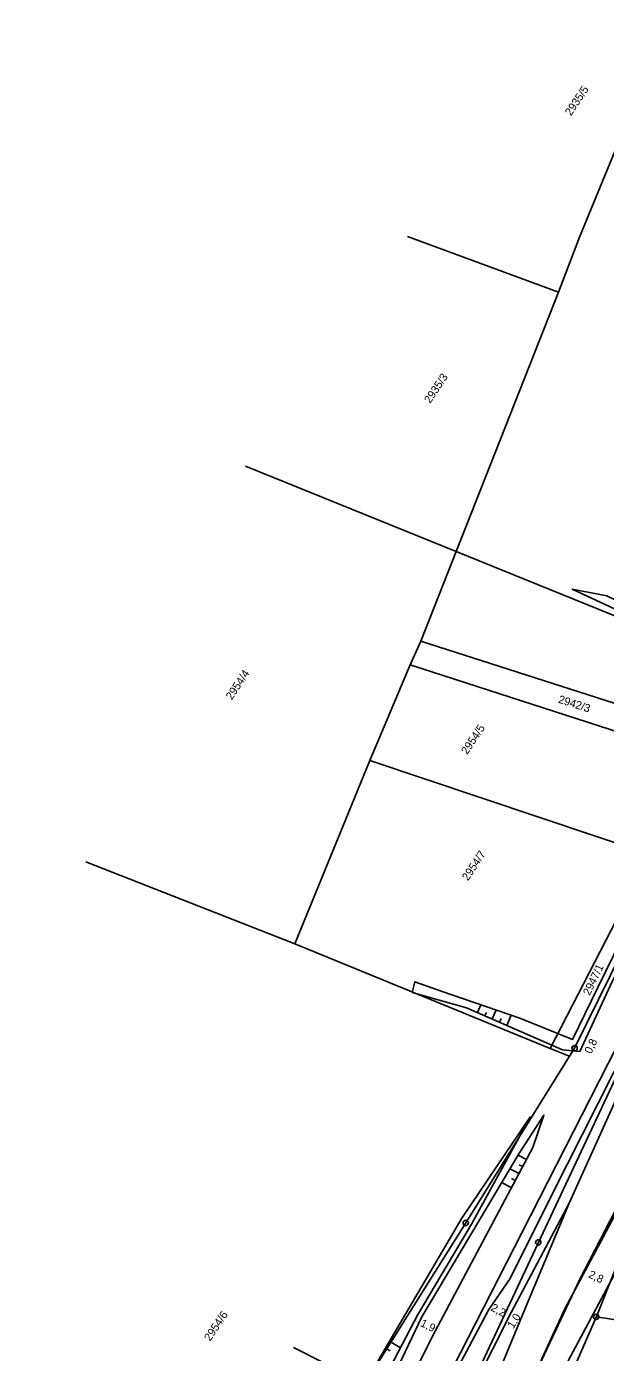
# Model space of a CAD drawing. Extents: x -658910 to -658078, y -1170373 to -1169331.
# Drawn here: x -658412.3 to -658303.7, y -1169709.4 to -1169460.8 of the extents above; entities that cross this region are included whole.
import ezdxf

# ---------------------------------------------------------------- set-up
doc = ezdxf.new("R2010")
doc.units = 0
for name, color, linetype in [('Vrstva 1', 7, 'Continuous'), ('Vrstva 10', 7, 'Continuous'), ('Vrstva 11', 7, 'Continuous'), ('Vrstva 6', 7, 'Continuous'), ('Vrstva 8', 7, 'Continuous'), ('Vrstva 9', 7, 'Continuous')]:
    doc.layers.add(name, color=color, linetype=linetype)

msp = doc.modelspace()

# ---------------------------------------------------------------- linework, layer by layer
at = {"layer": 'Vrstva 1'}
for p, q in [((-658309.53, -1169652.309), (-658309.43, -1169652.309)), ((-658329.96, -1169685.09), (-658329.86, -1169685.09)), ((-658305.402, -1169702.638), (-658309.852, -1169712.97)), ((-658305.491, -1169702.699), (-658305.391, -1169702.699)), ((-658279.77, -1169706.539), (-658305.441, -1169702.699))]:
    msp.add_line(p, q, dxfattribs=at)
msp.add_lwpolyline([(-658387.09, -1169803.74), (-658379.66, -1169787.031), (-658371.41, -1169770.08), (-658363.031, -1169753.09), (-658350.949, -1169718.6), (-658329.91, -1169685.09), (-658309.48, -1169652.309), (-658298.289, -1169629.6), (-658291.762, -1169617.34), (-658282.25, -1169598.42), (-658273.73, -1169581.691), (-658253.98, -1169552.23), (-658232.398, -1169524.699), (-658206.289, -1169500.25)], dxfattribs=at)
for centre in [(-658309.48, -1169652.309), (-658329.91, -1169685.09), (-658305.441, -1169702.699)]:
    msp.add_circle(centre, 0.499, dxfattribs=at)
at = {"layer": 'Vrstva 10'}
for points in [[(-658194.776, -1169460.194), (-658224.927, -1169485.893), (-658240.721, -1169499.622), (-658249.728, -1169509.51), (-658258.019, -1169520.955), (-658267.977, -1169530.234), (-658274.167, -1169537.438), (-658277.501, -1169544.636), (-658285.866, -1169562.195), (-658285.468, -1169565.535), (-658290.44, -1169573.844), (-658303.418, -1169567.527), (-658309.934, -1169566.284), (-658289.485, -1169575.785), (-658284.171, -1169566.065), (-658282.55, -1169561.267), (-658272.844, -1169546.971), (-658264.004, -1169532.154), (-658255.261, -1169522.447), (-658245.754, -1169510.106), (-658236.942, -1169502.039), (-658223.545, -1169490.595), (-658189.788, -1169462.569), (-658188.806, -1169458.731)], [(-658276.584, -1169590.485), (-658283.44, -1169602.541), (-658287.975, -1169611.492), (-658289.687, -1169613.574), (-658302.78, -1169640.536), (-658308.513, -1169652.938), (-658311.735, -1169652.624), (-658329.784, -1169644.735), (-658339.953, -1169641.872), (-658339.466, -1169639.877), (-658334.347, -1169641.667), (-658319.785, -1169646.697), (-658309.854, -1169650.681), (-658305.208, -1169641.097), (-658290.001, -1169610.092), (-658286.058, -1169602.153), (-658278.256, -1169587.533)], [(-658412.34, -1169868.25), (-658390.58, -1169825.61), (-658346.68, -1169740.23), (-658319.39, -1169686.96), (-658299.95, -1169648.82), (-658273.229, -1169598.35)], [(-658333.115, -1169751.576), (-658323.796, -1169728.025), (-658308.485, -1169695.615), (-658294.271, -1169668.043), (-658278.157, -1169639.847), (-658267.473, -1169621.543), (-658253.549, -1169598.254)], [(-658249.659, -1169600.535), (-658264.767, -1169623.458), (-658274.587, -1169639.486), (-658284.944, -1169658.621), (-658291.388, -1169672.25), (-658302.068, -1169694.842), (-658312.164, -1169713.774), (-658318.886, -1169726.345), (-658324.9, -1169737.364), (-658333.115, -1169751.576)], [(-658354.813, -1169800), (-658338.217, -1169761.133), (-658328.016, -1169737.523), (-658311.372, -1169701.327), (-658294.326, -1169669.378), (-658287.561, -1169657.031), (-658267.485, -1169620.8), (-658262.54, -1169612.307), (-658258.99, -1169605.547)], [(-658375.867, -1169800), (-658361.393, -1169773.644), (-658354.79, -1169760.67), (-658342.877, -1169737.984), (-658335.517, -1169720.03), (-658325.56, -1169701.303), (-658321.609, -1169695.48), (-658313.743, -1169679.786), (-658299.295, -1169651.229), (-658299.107, -1169647.523), (-658285.769, -1169623.061), (-658296.701, -1169647.814), (-658297.652, -1169652.866), (-658310.48, -1169681.38)], [(-658327.699, -1169645.646), (-658327.06, -1169644.184)], [(-658326.325, -1169646.248), (-658326.05, -1169645.619)], [(-658324.95, -1169646.848), (-658324.215, -1169645.167)], [(-658323.576, -1169647.449), (-658323.263, -1169646.732)], [(-658322.201, -1169648.049), (-658321.371, -1169646.149)], [(-658382.912, -1169798.852), (-658379.063, -1169792.65), (-658368.598, -1169771.356), (-658349.867, -1169733.694), (-658335.676, -1169705.398), (-658317.304, -1169670.927), (-658315.248, -1169664.852), (-658319.954, -1169672.137), (-658338.157, -1169702.661), (-658345.008, -1169717.114)], [(-658318.509, -1169673.188), (-658320.081, -1169672.35)], [(-658319.214, -1169674.511), (-658319.869, -1169674.163)], [(-658319.92, -1169675.835), (-658321.619, -1169674.929)], [(-658320.625, -1169677.159), (-658321.331, -1169676.783)], [(-658321.331, -1169678.482), (-658323.157, -1169677.509)], [(-658360.929, -1169800), (-658349.936, -1169774.389), (-658334.842, -1169739.91), (-658319.089, -1169701.899), (-658310.48, -1169681.38), (-658321.364, -1169701.87), (-658331.897, -1169722.678), (-658331.43, -1169723.306)], [(-658344.977, -1169708.574), (-658344.126, -1169709.075)], [(-658344.216, -1169707.281), (-658342.151, -1169708.496)]]:
    msp.add_lwpolyline(points, dxfattribs=at)
msp.add_lwpolyline([(-658317.755, -1169665.103), (-658330.637, -1169684.198), (-658348.724, -1169714.945), (-658354.376, -1169726.759), (-658358.535, -1169740.858), (-658350.866, -1169724.45), (-658347.054, -1169717.595), (-658346.228, -1169716.253), (-658338.94, -1169702.386), (-658328.834, -1169685.29)], close=True, dxfattribs=at)
at = {"layer": 'Vrstva 6'}
msp.add_lwpolyline([(-658362.224, -1169708.459), (-658345.008, -1169717.114), (-658322.313, -1169728.28)], dxfattribs=at)
at = {"layer": 'Vrstva 8'}
for p, q in [((-658316.353, -1169688.744), (-658316.253, -1169688.744)), ((-658301.781, -1169693.669), (-658305.402, -1169702.638))]:
    msp.add_line(p, q, dxfattribs=at)
for points in [[(-658308.539, -1169500.27), (-658295.859, -1169469.441), (-658284.391, -1169442.24)], [(-658312.48, -1169510.551), (-658340.828, -1169500.109)], [(-658282.48, -1169554.49), (-658296.57, -1169573.449), (-658331.68, -1169559.211), (-658312.48, -1169510.551), (-658308.539, -1169500.27)], [(-658314.059, -1169652.35), (-658295.309, -1169616), (-658286.199, -1169597.941), (-658283.891, -1169593.469), (-658276.852, -1169580.85), (-658266.91, -1169566.039), (-658264.172, -1169561.6), (-658257.539, -1169550.99), (-658245.52, -1169536.1), (-658234.621, -1169522.359), (-658224.73, -1169512.711), (-658221.309, -1169509.051), (-658215.941, -1169504.039), (-658211.672, -1169500.27)], [(-658331.68, -1169559.211), (-658371.262, -1169543.199)], [(-658362.012, -1169632.781), (-658347.898, -1169598.379), (-658340.34, -1169580.449), (-658338.34, -1169575.98), (-658331.68, -1169559.211)], [(-658283.891, -1169593.469), (-658338.34, -1169575.98)], [(-658286.199, -1169597.941), (-658340.34, -1169580.449)], [(-658295.309, -1169616), (-658347.898, -1169598.379)], [(-658401.18, -1169617.371), (-658362.012, -1169632.781), (-658314.059, -1169652.35), (-658310.301, -1169653.879)], [(-658340.286, -1169739.901), (-658283.367, -1169618.664)]]:
    msp.add_lwpolyline(points, dxfattribs=at)
msp.add_circle((-658316.303, -1169688.744), 0.499, dxfattribs=at)

# ---------------------------------------------------------------- texts
at = {"layer": 'Vrstva 11'}
for s, rotation, p in [('0,8', 64.65358, (-658306.375, -1169653.5)), ('2,8', 334.71291, (-658307.018, -1169695.248)), ('2,2', 332.00021, (-658325.354, -1169701.426)), ('1,0', 58.12361, (-658320.969, -1169705.024)), ('1,9', 333.36596, (-658338.561, -1169704.353))]:
    msp.add_text(s, height=1.5, rotation=rotation, dxfattribs=at).set_placement(p)
at = {"layer": 'Vrstva 9'}
for s, rotation, p in [('2935/5', 56.1528, (-658310.175, -1169477.609)), ('2935/3', 56.1528, (-658336.599, -1169531.55)), ('2954/4', 56.1528, (-658373.818, -1169587.127)), ('2942/3', 342.18873, (-658312.672, -1169587.52)), ('2954/5', 56.1528, (-658329.657, -1169597.369)), ('2954/7', 56.1528, (-658329.496, -1169621.035)), ('2947/1', 64.25269, (-658306.648, -1169642.552)), ('2954/6', 56.1528, (-658377.886, -1169707.365))]:
    msp.add_text(s, height=1.5, rotation=rotation, dxfattribs=at).set_placement(p)

doc.saveas('drawing.dxf')
